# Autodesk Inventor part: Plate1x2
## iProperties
Created: 2006-02
Part Number: Plate1x2
Material: Stainless Steel
Document SubType Name: Modeling
Designer: 40664
Mass: 267852 g
Surface Area: 67075 cm^2
Volume: 33150 cm^3
Density: 8.08 g/cm^3
CSToolsMass: 268.0
CSToolsVolume: 33150000.0
CSToolsArea: 67075.0
Author: 40664
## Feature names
1. Extrusion2
